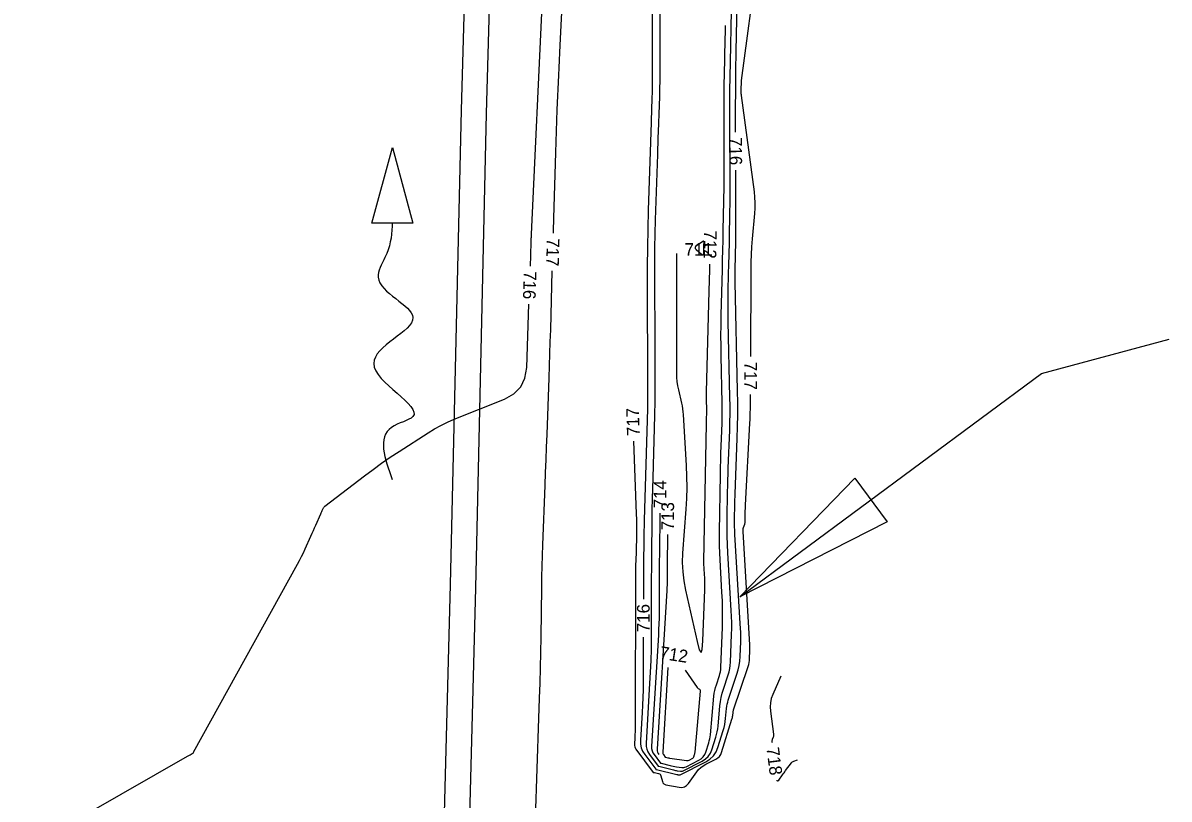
# Model space of a CAD drawing. Extents: x -361782338 to 28259792, y -263199453 to 8342113.
# Drawn here: x 1403671.2 to 1404033.4, y 577235.8 to 577481.2 of the extents above; entities that cross this region are included whole.
import ezdxf

# ---------------------------------------------------------------- set-up
doc = ezdxf.new("R2010")
doc.units = 0
for name, color, linetype in [('DT_X_Contour_Minor', 7, 'Continuous'), ('Level 19', 7, 'Continuous'), ('Level 40', 7, 'Continuous'), ('Level 56', 7, 'Continuous')]:
    doc.layers.add(name, color=color, linetype=linetype)

msp = doc.modelspace()

# ---------------------------------------------------------------- linework, layer by layer
at = {"layer": 'DT_X_Contour_Minor'}
for points in [[(1403838.86, 577414.74), (1403838.88, 577415.33), (1403839, 577419.39), (1403839.6, 577440.22), (1403839.71, 577443.58), (1403839.83, 577446.95), (1403839.96, 577450.31), (1403840.11, 577453.68), (1403840.62, 577464.67), (1403840.73, 577467.02), (1403840.84, 577469.38), (1403840.95, 577471.73), (1403841.06, 577474.09), (1403842.23, 577499.26)], [(1403870.13, 577500.04), (1403870.13, 577462.92), (1403870.12, 577461.6), (1403870.1, 577460.28), (1403870.07, 577458.96), (1403870.03, 577457.65), (1403869.87, 577453.34), (1403869.83, 577452.42), (1403869.8, 577451.5), (1403869.77, 577450.58), (1403869.74, 577449.66), (1403868.85, 577421.98), (1403868.68, 577416.05), (1403868.57, 577410.12), (1403868.51, 577404.19), (1403868.51, 577398.26), (1403868.61, 577367.61), (1403868.62, 577366.77), (1403868.62, 577365.93), (1403868.62, 577365.1), (1403868.62, 577364.26), (1403868.62, 577361.52), (1403868.62, 577360.94), (1403868.61, 577360.35), (1403868.6, 577359.76), (1403868.59, 577359.18), (1403867.56, 577323.98), (1403867.52, 577322.21), (1403867.48, 577320.43), (1403867.45, 577318.65), (1403867.42, 577316.87), (1403867.36, 577311.07), (1403867.35, 577309.83), (1403867.34, 577308.58), (1403867.33, 577307.34), (1403867.33, 577306.09), (1403867.31, 577299)], [(1403896.47, 577446.62), (1403896.47, 577447.97), (1403896.47, 577454), (1403896.5, 577460.04), (1403896.57, 577466.07), (1403896.68, 577472.1), (1403897.21, 577497.78)], [(1403901.24, 577375.7), (1403901.35, 577403.03), (1403901.39, 577405.49), (1403901.48, 577407.95), (1403901.62, 577410.41), (1403901.82, 577412.87), (1403902.55, 577420.9), (1403902.65, 577422.61), (1403902.66, 577424.33), (1403902.58, 577426.05), (1403902.4, 577427.76), (1403898.31, 577458.23), (1403898.28, 577458.48), (1403898.25, 577458.73), (1403898.24, 577458.98), (1403898.24, 577459.23), (1403898.23, 577460.05), (1403898.23, 577460.22), (1403898.24, 577460.4), (1403898.24, 577460.58), (1403898.24, 577460.75), (1403898.27, 577461.96), (1403898.27, 577462.22), (1403898.29, 577462.48), (1403898.31, 577462.74), (1403898.35, 577463), (1403903.29, 577499.97)], [(1403831.6, 577404.22), (1403831.73, 577407.68), (1403831.74, 577408.07), (1403831.76, 577408.46), (1403831.77, 577408.85), (1403831.78, 577409.24), (1403831.81, 577410.51), (1403831.82, 577410.79), (1403831.83, 577411.06), (1403831.84, 577411.33), (1403831.84, 577411.6), (1403831.89, 577413.09), (1403831.9, 577413.41), (1403831.91, 577413.73), (1403831.92, 577414.05), (1403831.94, 577414.37), (1403835.39, 577488.85)], [(1403872.49, 577487), (1403872.49, 577465.51), (1403872.48, 577462.93), (1403872.45, 577460.35), (1403872.39, 577457.77), (1403872.3, 577455.19), (1403871.98, 577446.76), (1403871.92, 577444.95), (1403871.85, 577443.14), (1403871.79, 577441.34), (1403871.73, 577439.53), (1403871.07, 577418.92), (1403870.95, 577414.51), (1403870.86, 577410.09), (1403870.82, 577405.67), (1403870.81, 577401.26), (1403870.89, 577379.2), (1403870.9, 577376.99), (1403870.9, 577374.79), (1403870.91, 577372.59), (1403870.91, 577370.39), (1403870.91, 577363.2), (1403870.91, 577361.66), (1403870.89, 577360.12), (1403870.86, 577358.58), (1403870.82, 577357.04), (1403870.25, 577337.36), (1403870.16, 577334.02), (1403870.09, 577330.68), (1403870.03, 577327.34), (1403869.99, 577323.99), (1403869.87, 577313.08), (1403869.85, 577310.74), (1403869.83, 577308.4), (1403869.82, 577306.07), (1403869.81, 577303.73), (1403869.75, 577286.79), (1403869.72, 577283.17), (1403869.63, 577279.54), (1403869.48, 577275.92), (1403869.29, 577272.29), (1403868.14, 577253.4), (1403868.17, 577252.44), (1403868.35, 577251.53), (1403868.7, 577250.66), (1403869.2, 577249.85)], [(1403869.2, 577249.85), (1403871.96, 577246.16), (1403871.97, 577246.14), (1403871.99, 577246.13), (1403872.01, 577246.13), (1403872.04, 577246.13), (1403872.11, 577246.14), (1403872.13, 577246.14), (1403872.15, 577246.14), (1403872.17, 577246.14), (1403872.18, 577246.14), (1403876.81, 577244.97), (1403877.11, 577244.9), (1403877.41, 577244.84), (1403877.72, 577244.78), (1403878.02, 577244.73), (1403879.03, 577244.59), (1403879.24, 577244.58), (1403879.45, 577244.59), (1403879.65, 577244.64), (1403879.85, 577244.73), (1403885.93, 577247.8), (1403886.97, 577248.45), (1403887.83, 577249.27), (1403888.49, 577250.24), (1403888.97, 577251.38), (1403890.2, 577255.35), (1403890.45, 577256.21), (1403890.64, 577257.08), (1403890.79, 577257.95), (1403890.9, 577258.83), (1403891.49, 577265.23), (1403891.65, 577266.59), (1403891.9, 577267.93), (1403892.22, 577269.26), (1403892.62, 577270.57), (1403894.13, 577275.08), (1403894.42, 577276.05), (1403894.64, 577277.03), (1403894.78, 577278.03), (1403894.85, 577279.04), (1403895.18, 577287.86), (1403895.22, 577289.75), (1403895.22, 577291.63), (1403895.18, 577293.52), (1403895.09, 577295.41), (1403894, 577313.6), (1403893.87, 577316.26), (1403893.79, 577318.92), (1403893.76, 577321.58), (1403893.78, 577324.24), (1403893.93, 577332.95), (1403893.97, 577334.81), (1403894.02, 577336.68), (1403894.07, 577338.54), (1403894.14, 577340.41), (1403894.59, 577352.41), (1403894.67, 577354.98), (1403894.71, 577357.56), (1403894.71, 577360.13), (1403894.67, 577362.7), (1403894.12, 577386.73), (1403894.08, 577389.3), (1403894.07, 577391.87), (1403894.09, 577394.44), (1403894.14, 577397.01), (1403894.36, 577405.4), (1403894.4, 577407.2), (1403894.44, 577409), (1403894.48, 577410.8), (1403894.51, 577412.6), (1403894.67, 577421.73), (1403894.7, 577423.68), (1403894.72, 577425.64), (1403894.72, 577427.6), (1403894.72, 577429.55), (1403894.65, 577450.64), (1403894.65, 577455.16), (1403894.68, 577459.67), (1403894.73, 577464.19), (1403894.81, 577468.71), (1403895.15, 577485.01)], [(1403870.69, 577249.84), (1403872.72, 577247.12), (1403872.73, 577247.11), (1403872.74, 577247.1), (1403872.76, 577247.1), (1403872.78, 577247.1), (1403872.83, 577247.11), (1403872.85, 577247.11), (1403872.86, 577247.11), (1403872.87, 577247.11), (1403872.88, 577247.11), (1403875.74, 577246.39), (1403876.24, 577246.27), (1403876.74, 577246.17), (1403877.25, 577246.07), (1403877.75, 577245.99), (1403879.42, 577245.76), (1403879.77, 577245.73), (1403880.12, 577245.76), (1403880.45, 577245.85), (1403880.78, 577245.98), (1403884.85, 577248.04), (1403885.61, 577248.52), (1403886.24, 577249.11), (1403886.72, 577249.82), (1403887.07, 577250.65), (1403887.97, 577253.55), (1403888.15, 577254.17), (1403888.29, 577254.8), (1403888.4, 577255.44), (1403888.48, 577256.09), (1403889.6, 577268.29), (1403889.71, 577269.21), (1403889.88, 577270.12), (1403890.1, 577271.02), (1403890.37, 577271.91), (1403891.34, 577274.8), (1403891.52, 577275.42), (1403891.66, 577276.05), (1403891.75, 577276.69), (1403891.8, 577277.34), (1403892.27, 577290.17), (1403892.34, 577292.92), (1403892.34, 577295.67), (1403892.27, 577298.42), (1403892.14, 577301.17), (1403891.53, 577311.44), (1403891.42, 577313.65), (1403891.35, 577315.85), (1403891.33, 577318.05), (1403891.34, 577320.26), (1403891.66, 577338.4), (1403891.71, 577340.64), (1403891.76, 577342.88), (1403891.83, 577345.11), (1403891.91, 577347.35), (1403892.18, 577354.67), (1403892.23, 577356.23), (1403892.26, 577357.8), (1403892.26, 577359.37), (1403892.23, 577360.94), (1403891.89, 577375.91), (1403891.84, 577379.12), (1403891.82, 577382.33), (1403891.85, 577385.54), (1403891.91, 577388.74), (1403892.29, 577403.16), (1403892.36, 577406.26), (1403892.43, 577409.35), (1403892.5, 577412.44), (1403892.55, 577415.53), (1403892.79, 577429.57), (1403892.84, 577432.58), (1403892.87, 577435.59), (1403892.88, 577438.6), (1403892.88, 577441.6), (1403892.84, 577454), (1403892.84, 577456.65), (1403892.85, 577459.31), (1403892.88, 577461.97), (1403892.93, 577464.62), (1403893.17, 577475.96), (1403893.22, 577478.39), (1403893.25, 577480.31)], [(1403867.27, 577287), (1403867.22, 577272.74), (1403867.19, 577270.33), (1403867.13, 577267.92), (1403867.04, 577265.51), (1403866.91, 577263.1), (1403866.38, 577254.36), (1403866.41, 577253.14), (1403866.64, 577251.98), (1403867.08, 577250.88), (1403867.73, 577249.84), (1403871.2, 577245.19), (1403871.22, 577245.17), (1403871.24, 577245.16), (1403871.27, 577245.15), (1403871.3, 577245.15), (1403871.4, 577245.17), (1403871.42, 577245.17), (1403871.44, 577245.17), (1403871.46, 577245.17), (1403871.48, 577245.17), (1403877.88, 577243.56), (1403877.98, 577243.53), (1403878.09, 577243.51), (1403878.19, 577243.49), (1403878.29, 577243.47), (1403878.64, 577243.42), (1403878.71, 577243.42), (1403878.78, 577243.43), (1403878.85, 577243.44), (1403878.92, 577243.47), (1403887.01, 577247.56), (1403888.33, 577248.39), (1403889.42, 577249.42), (1403890.26, 577250.66), (1403890.86, 577252.11), (1403892.53, 577257.47), (1403892.8, 577258.4), (1403893.01, 577259.34), (1403893.18, 577260.3), (1403893.29, 577261.26), (1403893.58, 577264.43), (1403893.67, 577265.11), (1403893.79, 577265.77), (1403893.95, 577266.43), (1403894.14, 577267.08), (1403896.89, 577275.24), (1403897.3, 577276.62), (1403897.6, 577278.02), (1403897.81, 577279.43), (1403897.91, 577280.86), (1403898.08, 577285.57), (1403898.11, 577286.58), (1403898.11, 577287.59), (1403898.09, 577288.6), (1403898.04, 577289.61), (1403896.26, 577319.44), (1403896.19, 577320.71), (1403896.15, 577321.99), (1403896.14, 577323.26), (1403896.15, 577324.53), (1403896.22, 577328.7), (1403896.24, 577329.59), (1403896.26, 577330.48), (1403896.29, 577331.37), (1403896.32, 577332.26), (1403896.98, 577349.8), (1403897.1, 577353.55), (1403897.15, 577357.31), (1403897.15, 577361.07), (1403897.1, 577364.83), (1403896.31, 577399.23), (1403896.3, 577400.32), (1403896.29, 577401.41), (1403896.3, 577402.5), (1403896.32, 577403.58), (1403896.41, 577407.13), (1403896.43, 577407.89), (1403896.45, 577408.66), (1403896.46, 577409.42), (1403896.48, 577410.18), (1403896.55, 577414.04), (1403896.56, 577414.87), (1403896.57, 577415.7), (1403896.57, 577416.52), (1403896.57, 577417.35), (1403896.51, 577434.62)], [(1403883.98, 577409.54), (1403885.71, 577408.07), (1403886, 577407.87), (1403886.21, 577407.86), (1403886.34, 577408.02), (1403886.39, 577408.37), (1403886.43, 577409.8), (1403886.43, 577410.09), (1403886.44, 577410.38), (1403886.44, 577410.67), (1403886.45, 577410.96), (1403886.47, 577411.9), (1403886.45, 577412.06), (1403886.39, 577412.15), (1403886.28, 577412.16), (1403886.14, 577412.08), (1403884.06, 577410.71), (1403883.75, 577410.44), (1403883.63, 577410.15), (1403883.71, 577409.86), (1403883.98, 577409.54)], [(1403877.75, 577408.3), (1403877.76, 577403.96), (1403877.76, 577402.66), (1403877.77, 577401.37), (1403877.77, 577400.08), (1403877.77, 577398.78), (1403877.78, 577370.41), (1403877.82, 577369.09), (1403877.93, 577367.78), (1403878.11, 577366.48), (1403878.37, 577365.19), (1403879.33, 577360.98), (1403879.52, 577360.07), (1403879.66, 577359.16), (1403879.78, 577358.25), (1403879.85, 577357.32), (1403880.81, 577341.21), (1403880.96, 577337.76), (1403880.99, 577334.3), (1403880.91, 577330.85), (1403880.72, 577327.4), (1403879.72, 577313.57), (1403879.61, 577310.61), (1403879.73, 577307.67), (1403880.06, 577304.75), (1403880.6, 577301.84), (1403884.29, 577285.6), (1403884.99, 577283), (1403885.53, 577282.16), (1403885.91, 577283.09), (1403886.13, 577285.77), (1403886.72, 577301.97), (1403886.74, 577302.86), (1403886.74, 577303.76), (1403886.72, 577304.65), (1403886.68, 577305.54), (1403886.5, 577308.46), (1403886.47, 577309.09), (1403886.45, 577309.71), (1403886.45, 577310.34), (1403886.45, 577310.96), (1403887.21, 577354.37), (1403887.22, 577354.82), (1403887.23, 577355.27), (1403887.24, 577355.73), (1403887.26, 577356.18), (1403887.32, 577357.66), (1403887.32, 577357.97), (1403887.33, 577358.29), (1403887.33, 577358.61), (1403887.32, 577358.92), (1403887.26, 577361.95), (1403887.25, 577362.6), (1403887.24, 577363.25), (1403887.25, 577363.89), (1403887.26, 577364.54), (1403888.09, 577396.4), (1403888.26, 577403.22), (1403888.3, 577404.9)], [(1403833.31, 577232.77), (1403833.4, 577235.9), (1403833.5, 577239.03), (1403834.5, 577267.66), (1403834.66, 577272.47), (1403834.79, 577277.29), (1403834.9, 577282.11), (1403834.98, 577286.92), (1403835.21, 577302.66), (1403835.27, 577306.03), (1403835.34, 577309.41), (1403835.44, 577312.78), (1403835.56, 577316.15), (1403836.27, 577334.96), (1403836.42, 577338.99), (1403836.57, 577343.02), (1403836.72, 577347.05), (1403836.87, 577351.09), (1403837.52, 577368.91), (1403837.66, 577372.72), (1403837.78, 577376.54), (1403837.9, 577380.36), (1403838.01, 577384.18), (1403838.52, 577402.74)], [(1403671.23, 577219.51), (1403723.29, 577249.31), (1403723.49, 577249.42), (1403723.69, 577249.54), (1403723.89, 577249.65), (1403724.09, 577249.77), (1403724.74, 577250.14), (1403724.87, 577250.23), (1403724.99, 577250.33), (1403725.09, 577250.45), (1403725.18, 577250.58), (1403757.99, 577310.01), (1403758.64, 577311.21), (1403759.26, 577312.42), (1403759.85, 577313.64), (1403760.42, 577314.88), (1403762.23, 577318.94), (1403762.62, 577319.8), (1403763.01, 577320.67), (1403763.4, 577321.54), (1403763.79, 577322.41), (1403765.39, 577325.99), (1403765.5, 577326.24), (1403765.61, 577326.49), (1403765.73, 577326.74), (1403765.84, 577326.99), (1403766.2, 577327.81), (1403766.29, 577327.98), (1403766.4, 577328.13), (1403766.52, 577328.27), (1403766.67, 577328.39), (1403779.2, 577338.01), (1403781.87, 577340.01), (1403784.58, 577341.96), (1403787.33, 577343.85), (1403790.11, 577345.69), (1403799.28, 577351.6), (1403801.27, 577352.81), (1403803.32, 577353.93), (1403805.41, 577354.95), (1403807.55, 577355.87), (1403823.38, 577362.21), (1403826.36, 577363.85), (1403828.53, 577366.07), (1403829.89, 577368.86), (1403830.43, 577372.23), (1403831.16, 577392.23)], [(1403901.12, 577359.09), (1403901.17, 577362.72), (1403901.18, 577363.5), (1403901.18, 577363.71)], [(1403864.23, 577348.93), (1403865.08, 577325.93), (1403865.13, 577324.12), (1403865.16, 577322.3), (1403865.15, 577320.48), (1403865.11, 577318.66), (1403864.88, 577310.61), (1403864.87, 577310.4), (1403864.87, 577310.18), (1403864.86, 577309.97), (1403864.86, 577309.76), (1403864.85, 577309.06), (1403864.85, 577308.91), (1403864.85, 577308.76), (1403864.85, 577308.61), (1403864.85, 577308.46), (1403864.68, 577257.5), (1403864.67, 577256.9), (1403864.66, 577256.3), (1403864.64, 577255.69), (1403864.6, 577255.09), (1403864.48, 577253.12), (1403864.49, 577252.71), (1403864.57, 577252.32), (1403864.72, 577251.94), (1403864.94, 577251.6), (1403870.44, 577244.22), (1403870.46, 577244.2), (1403870.49, 577244.18), (1403870.52, 577244.18), (1403870.56, 577244.18), (1403870.68, 577244.2), (1403870.7, 577244.2), (1403870.73, 577244.2), (1403870.75, 577244.2), (1403870.78, 577244.2), (1403872.12, 577243.86), (1403872.38, 577243.76), (1403872.58, 577243.61), (1403872.74, 577243.4), (1403872.84, 577243.15), (1403873.36, 577241.28), (1403873.5, 577240.92), (1403873.73, 577240.64), (1403874.02, 577240.44), (1403874.39, 577240.33), (1403878.63, 577239.53), (1403879.49, 577239.48), (1403880.26, 577239.65), (1403880.94, 577240.05), (1403881.53, 577240.69), (1403884.17, 577244.35), (1403884.78, 577245.09), (1403885.46, 577245.74), (1403886.21, 577246.31), (1403887.04, 577246.79), (1403890.23, 577248.4), (1403890.85, 577248.79), (1403891.37, 577249.28), (1403891.77, 577249.86), (1403892.05, 577250.55), (1403895.31, 577261.01), (1403895.39, 577261.3), (1403895.46, 577261.6), (1403895.51, 577261.9), (1403895.55, 577262.2), (1403895.64, 577263.19), (1403895.66, 577263.4), (1403895.7, 577263.6), (1403895.75, 577263.81), (1403895.81, 577264.01), (1403900.39, 577277.64), (1403900.59, 577278.3), (1403900.74, 577278.97), (1403900.83, 577279.64), (1403900.88, 577280.33), (1403900.97, 577282.59), (1403900.98, 577283.07), (1403900.98, 577283.55), (1403900.97, 577284.03), (1403900.94, 577284.52), (1403898.8, 577320.4), (1403898.8, 577320.72), (1403898.83, 577321.04), (1403898.88, 577321.36), (1403898.97, 577321.67), (1403899.32, 577322.68), (1403899.39, 577322.9), (1403899.43, 577323.12), (1403899.46, 577323.35), (1403899.47, 577323.57), (1403899.5, 577326.36), (1403899.51, 577326.96), (1403899.53, 577327.56), (1403899.55, 577328.15), (1403899.58, 577328.75), (1403900.97, 577354.64), (1403901.03, 577355.75), (1403901.07, 577356.86), (1403901.1, 577357.97), (1403901.12, 577359.09)], [(1403872.5, 577326.16), (1403872.37, 577313.35), (1403872.34, 577310.79), (1403872.32, 577308.23), (1403872.31, 577305.67), (1403872.3, 577303.11), (1403872.27, 577294.74), (1403872.25, 577292.95), (1403872.21, 577291.16), (1403872.14, 577289.37), (1403872.04, 577287.58), (1403869.91, 577252.46), (1403869.92, 577251.75), (1403870.06, 577251.08), (1403870.31, 577250.44), (1403870.69, 577249.84)], [(1403874.92, 577319.43), (1403874.82, 577309.63), (1403874.81, 577308.84), (1403874.8, 577308.05), (1403874.8, 577307.26), (1403874.8, 577306.47), (1403874.79, 577303.89), (1403874.78, 577303.33), (1403874.77, 577302.78), (1403874.75, 577302.23), (1403874.72, 577301.67), (1403871.67, 577251.52), (1403871.68, 577251.06), (1403871.77, 577250.63), (1403871.93, 577250.22), (1403872.17, 577249.84)], [(1403875.07, 577277.42), (1403873.44, 577250.58), (1403873.44, 577250.38), (1403873.48, 577250.18), (1403873.55, 577250), (1403873.66, 577249.83)], [(1403873.66, 577249.83), (1403874.24, 577249.06), (1403874.24, 577249.05), (1403874.25, 577249.05), (1403874.25, 577249.05), (1403874.25, 577249.05), (1403874.27, 577249.05), (1403874.28, 577249.05), (1403874.28, 577249.05), (1403874.28, 577249.05), (1403874.29, 577249.05), (1403875.05, 577248.86), (1403875.22, 577248.82), (1403875.39, 577248.79), (1403875.55, 577248.75), (1403875.72, 577248.73), (1403880.94, 577247.99), (1403881.21, 577247.97), (1403881.47, 577247.99), (1403881.73, 577248.05), (1403881.98, 577248.16), (1403882.78, 577248.56), (1403882.94, 577248.66), (1403883.07, 577248.78), (1403883.17, 577248.93), (1403883.24, 577249.1), (1403883.49, 577249.91), (1403883.54, 577250.09), (1403883.58, 577250.26), (1403883.61, 577250.44), (1403883.63, 577250.62), (1403885.41, 577269.86), (1403885.4, 577270.02), (1403885.36, 577270.15), (1403885.28, 577270.27), (1403885.16, 577270.37), (1403884.71, 577270.68), (1403884.62, 577270.75), (1403884.53, 577270.82), (1403884.46, 577270.91), (1403884.39, 577271), (1403880.61, 577276.57)], [(1403910.71, 577274.67), (1403908.19, 577268.81), (1403907.74, 577267.54), (1403907.47, 577266.25), (1403907.38, 577264.93), (1403907.47, 577263.59), (1403908.46, 577256.3), (1403908.48, 577256.06), (1403908.46, 577255.81), (1403908.42, 577255.57), (1403908.34, 577255.34), (1403908.03, 577254.57), (1403907.98, 577254.4), (1403907.95, 577254.24), (1403907.94, 577254.06), (1403907.95, 577253.89), (1403907.98, 577253.67)], [(1403909.49, 577241.77), (1403909.53, 577241.63), (1403909.66, 577241.49), (1403909.84, 577241.54), (1403910.08, 577241.8), (1403911.26, 577243.39), (1403911.51, 577243.73), (1403911.76, 577244.08), (1403912.02, 577244.42), (1403912.27, 577244.76), (1403914.1, 577247.23), (1403914.26, 577247.42), (1403914.44, 577247.58), (1403914.65, 577247.7), (1403914.88, 577247.8), (1403915.99, 577248.17)]]:
    msp.add_lwpolyline(points, dxfattribs=at)
at = {"layer": 'Level 40'}
for p, q in [((1403897.79, 577299.67), (1403934.12, 577337.27)), ((1403934.12, 577337.27), (1403944.35, 577323.47)), ((1403944.35, 577323.47), (1403897.79, 577299.67))]:
    msp.add_line(p, q, dxfattribs=at)
msp.add_lwpolyline([(1403897.79, 577299.67), (1403993.13, 577370.33), (1404033.44, 577381.14)], dxfattribs=at)
at = {"layer": 'Level 56'}
for p, q in [((1403781.53, 577417.83), (1403788.01, 577441.82)), ((1403788.01, 577441.82), (1403794.41, 577417.81)), ((1403794.41, 577417.81), (1403781.53, 577417.83))]:
    msp.add_line(p, q, dxfattribs=at)
for points in [[(1403799.72, 576951.13), (1403799.37, 577003.24), (1403799.52, 577053.24), (1403800.45, 577093.03), (1403801.13, 577118.22), (1403803.77, 577203.2), (1403806.32, 577303.59), (1403809.79, 577453.55), (1403811.89, 577528.32), (1403813.35, 577578.3), (1403815.32, 577653.47), (1403817.33, 577718.44), (1403820.35, 577828.2), (1403822.42, 577903.37), (1403824.98, 578003.34), (1403826.21, 578053.33), (1403828.88, 578143.09), (1403833.01, 578278.03), (1403835.33, 578353.19), (1403836.58, 578403.18), (1403837.59, 578489.24)], [(1403807.71, 576950.11), (1403807.36, 577002.22), (1403807.51, 577052.22), (1403808.43, 577092.01), (1403809.12, 577117.2), (1403811.75, 577202.18), (1403814.31, 577302.57), (1403817.77, 577452.53), (1403819.88, 577527.3), (1403821.33, 577577.28), (1403823.31, 577652.45), (1403825.32, 577717.42), (1403828.34, 577827.18), (1403830.4, 577902.36), (1403832.96, 578002.32), (1403834.2, 578052.31), (1403836.87, 578142.07), (1403841, 578277.01), (1403843.32, 578352.18), (1403844.57, 578402.16), (1403845.58, 578488.22)]]:
    msp.add_lwpolyline(points, dxfattribs=at)
msp.add_spline([(1403787.91, 577417.84), (1403787.91, 577416.89), (1403785.65, 577407.02), (1403783.47, 577400.77), (1403794.48, 577388.04), (1403782.09, 577373.5), (1403794.45, 577356.69), (1403787.74, 577353.29), (1403787.9, 577336.82)], degree=3, dxfattribs=at)

# ---------------------------------------------------------------- texts
at = {"layer": 'Level 19'}
for s, rotation, p in [('716', 270.187, (1403894.48, 577445.09)), ('712', 268.7733, (1403886.53, 577415.58)), ('717', 268.3876, (1403836.82, 577413.17)), ('716', 267.9045, (1403829.55, 577402.77)), ('717', 269.7298, (1403899.23, 577374.09)), ('717', 91.6624, (1403866.14, 577350.61)), ('714', 89.3906, (1403874.51, 577327.67)), ('713', 89.4058, (1403876.93, 577320.73)), ('716', 89.8101, (1403869.27, 577288.52)), ('712', 351.3252, (1403872.23, 577280.17)), ('718', 277.2721, (1403906.17, 577251.95))]:
    msp.add_text(s, height=4, rotation=rotation, dxfattribs=at).set_placement(p)
msp.add_text('711', height=4, dxfattribs=at).set_placement((1403880.33, 577407.54))

doc.saveas('drawing.dxf')
